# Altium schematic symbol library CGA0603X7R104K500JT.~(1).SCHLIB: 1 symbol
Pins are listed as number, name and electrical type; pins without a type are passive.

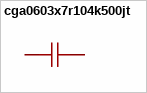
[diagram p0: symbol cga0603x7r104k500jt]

## cga0603x7r104k500jt
designator C??  (value not drawn)
容值:100nF;精度:±10%;额定电压:50V;温度系数:X7R;; Manufacturer: HRE(芯声); AddInBom: yes; ModelId: ac125912035d415993ca9572d50418b1; ModelName: C0603_L1.6-W0.8-H0.8; ModelTransform: 62.992,31.496,0,0,0,0,0,0,0; Value: 100nF; Tolerance: ±10%; Voltage Rating: 50V; Temperature Coefficient: X7R
footprint C0603
pins: 1, 2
